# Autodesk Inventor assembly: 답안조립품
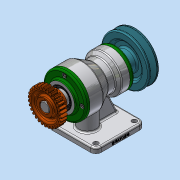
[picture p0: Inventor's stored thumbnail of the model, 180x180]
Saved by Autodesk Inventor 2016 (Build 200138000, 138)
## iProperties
Created: 2019-01
Part Number: 답안조립품
Material: 일반
Document SubType Name: Assembly
Designer: Administrator
Author: Administrator
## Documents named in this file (15)
- C:\Users\Administrator\Desktop\490108V1008\답안조립품.iam
- C:\Users\Administrator\Desktop\490108V1008\본체.ipt
- C:\Users\Administrator\Desktop\490108V1008\축.ipt
- C:\Users\Administrator\Desktop\490108V1008\뒤커버.ipt
- C:\Users\Administrator\Desktop\490108V1008\베어링 6203.ipt
- C:\Users\Administrator\Desktop\490108V1008\베어링 6205.ipt
- C:\Users\Administrator\Desktop\490108V1008\앞커버.ipt
- C:\Users\Administrator\Desktop\490108V1008\오일 실 17 30 8.ipt
- C:\Users\Administrator\Desktop\490108V1008\오일 실 25 38 8.ipt
- C:\Users\Administrator\Desktop\490108V1008\볼트 M4.ipt
- C:\Users\Administrator\Desktop\490108V1008\키 5 x 5 x 20.ipt
- C:\Users\Administrator\Desktop\490108V1008\키 6 x 6 x 18.ipt
- C:\Users\Administrator\Desktop\490108V1008\스퍼기어.ipt
- C:\Users\Administrator\Desktop\490108V1008\V-벨트풀리.ipt
- C:\Users\Administrator\Desktop\490108V1008\멈춤나사 M3.ipt
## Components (1 placed, 1 different names)
1. V-벨트풀리:1
